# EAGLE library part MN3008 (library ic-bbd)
2048-Stage Lo Noise BBD
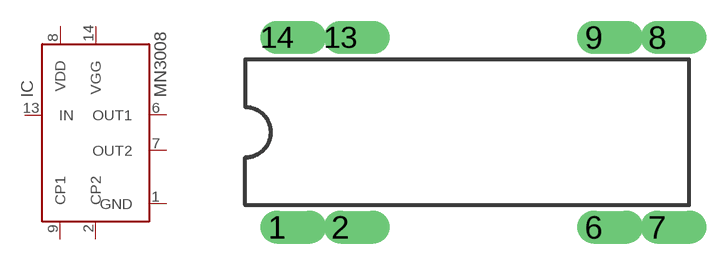
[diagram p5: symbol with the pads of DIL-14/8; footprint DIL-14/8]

Designator prefix IC

## MN3008  [DIL-14/8]
1  GND
2  CP2
6  OUT1
7  OUT2
8  VDD
9  CP1
13  IN
14  VGG

## Footprint DIL-14/8 (pad centres in mm)
Dual In Line Package
drill 0.813 offset: 1 -7.62,-3.81; 2 -5.08,-3.81; 6 5.08,-3.81; 7 7.62,-3.81; 8 7.62,3.81; 9 5.08,3.81; 13 -5.08,3.81; 14 -7.62,3.81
